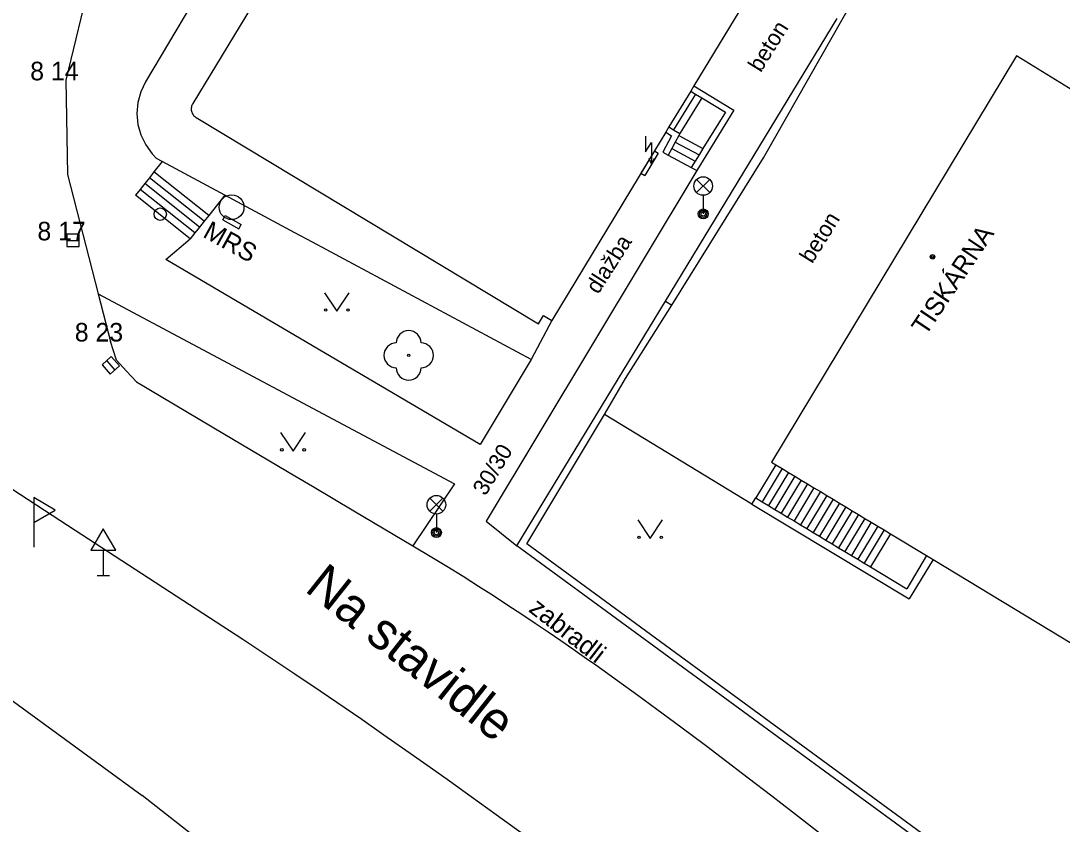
# Model space of a CAD drawing. Extents: x -538441 to -536770, y -1181008 to -1179809.
# Drawn here: x -538161.78 to -538119.74, y -1180887.51 to -1180855.09 of the extents above; entities that cross this region are included whole.
import ezdxf

# ---------------------------------------------------------------- set-up
doc = ezdxf.new("R2010")
doc.units = 0
for name, color, linetype in [('Vrstva 10', 7, 'Continuous'), ('Vrstva 11', 7, 'Continuous'), ('Vrstva 22', 7, 'Continuous'), ('Vrstva 24', 7, 'Continuous'), ('Vrstva 27', 7, 'Continuous'), ('Vrstva 28', 7, 'Continuous'), ('Vrstva 31', 7, 'Continuous'), ('Vrstva 33', 7, 'Continuous'), ('Vrstva 34', 7, 'Continuous'), ('Vrstva 36', 7, 'Continuous'), ('Vrstva 39', 7, 'Continuous'), ('Vrstva 4', 7, 'Continuous'), ('Vrstva 40', 7, 'Continuous'), ('Vrstva 41', 7, 'Continuous'), ('Vrstva 49', 7, 'Continuous'), ('Vrstva 5', 7, 'Continuous'), ('Vrstva 7', 7, 'Continuous'), ('Vrstva 8', 7, 'Continuous')]:
    doc.layers.add(name, color=color, linetype=linetype)

msp = doc.modelspace()

# ---------------------------------------------------------------- linework, layer by layer
at = {"layer": 'Vrstva 10'}
for p, q in [((-538158.99, -1180853.47), (-538159.96, -1180857.49)), ((-538159.96, -1180857.49), (-538159.89, -1180861.29)), ((-538159.58, -1180875.66), (-538166.34, -1180871.26)), ((-538152.82, -1180880.06), (-538159.58, -1180875.66))]:
    msp.add_line(p, q, dxfattribs=at)
for points in [[(-538159.89, -1180861.29), (-538158.655, -1180866.101), (-538158.16, -1180868.03)], [(-538157.11, -1180869.66), (-538157.51, -1180869.22), (-538157.91, -1180868.78), (-538158.16, -1180868.03)], [(-538157.11, -1180869.66), (-538153.555, -1180871.766), (-538150.718, -1180873.446)], [(-538150.718, -1180873.446), (-538150, -1180873.871), (-538148.334, -1180874.858), (-538145.95, -1180876.27), (-538145.251, -1180876.688), (-538144.577, -1180877.1), (-538143.927, -1180877.503), (-538143.301, -1180877.899), (-538142.698, -1180878.286)], [(-538142.698, -1180878.286), (-538142.115, -1180878.665), (-538141.553, -1180879.036), (-538141.011, -1180879.399), (-538140.487, -1180879.752), (-538139.982, -1180880.098), (-538139.494, -1180880.435), (-538139.022, -1180880.763), (-538138.566, -1180881.083), (-538137.687, -1180881.709), (-538136.866, -1180882.301), (-538136.1, -1180882.86), (-538135.384, -1180883.389), (-538134.715, -1180883.887)], [(-538150.718, -1180881.448), (-538151.406, -1180880.99), (-538152.82, -1180880.06)], [(-538144.474, -1180885.775), (-538145.248, -1180885.225), (-538145.926, -1180884.746), (-538147.117, -1180883.911), (-538148.013, -1180883.289), (-538148.687, -1180882.826), (-538149.7, -1180882.134), (-538150.718, -1180881.448)], [(-538134.715, -1180883.887), (-538134.089, -1180884.356)], [(-538134.089, -1180884.356), (-538133.504, -1180884.799), (-538132.409, -1180885.632), (-538131.455, -1180886.366), (-538130.621, -1180887.01), (-538129.166, -1180888.143)], [(-538136.93, -1180891.271), (-538138.634, -1180890.014), (-538140.127, -1180888.918), (-538141.437, -1180887.964), (-538142.584, -1180887.132), (-538143.591, -1180886.407), (-538144.474, -1180885.775)]]:
    msp.add_lwpolyline(points, dxfattribs=at)
at = {"layer": 'Vrstva 11'}
for p, q in [((-538134.605, -1180857.711), (-538132.99, -1180858.69)), ((-538134.542, -1180858.042), (-538135.427, -1180859.482)), ((-538134.285, -1180858.198), (-538135.171, -1180859.639)), ((-538132.99, -1180858.69), (-538134.49, -1180861.13)), ((-538135.504, -1180859.73), (-538135.86, -1180860.39)), ((-538135.741, -1180859.586), (-538135.504, -1180859.73)), ((-538135.213, -1180859.717), (-538134.238, -1180860.242)), ((-538135.498, -1180860.245), (-538134.553, -1180860.754)), ((-538135.355, -1180859.981), (-538134.395, -1180860.498)), ((-538135.86, -1180860.39), (-538135.64, -1180860.509)), ((-538135.64, -1180860.509), (-538134.71, -1180861.01)), ((-538154.195, -1180862.939), (-538156.405, -1180861.189)), ((-538134.49, -1180861.13), (-538142.99, -1180875.28)), ((-538134.71, -1180861.01), (-538134.49, -1180861.13)), ((-538154.381, -1180863.174), (-538156.591, -1180861.424)), ((-538154.753, -1180863.644), (-538156.963, -1180861.894)), ((-538154.567, -1180863.409), (-538156.777, -1180861.659)), ((-538154.94, -1180863.88), (-538157.15, -1180862.13)), ((-538155.92, -1180864.72), (-538154.94, -1180863.88)), ((-538150, -1180868.208), (-538155.92, -1180864.72)), ((-538158.655, -1180866.101), (-538150, -1180870.715)), ((-538143.24, -1180872.19), (-538150, -1180868.208)), ((-538141.18, -1180868.76), (-538143.24, -1180872.19)), ((-538150, -1180870.715), (-538144.27, -1180873.77)), ((-538132.26, -1180874.6), (-538138.22, -1180870.97)), ((-538131.3, -1180873.004), (-538132.106, -1180874.343)), ((-538131.042, -1180873.158), (-538131.848, -1180874.498)), ((-538130.784, -1180873.312), (-538131.59, -1180874.652)), ((-538144.27, -1180873.77), (-538145.95, -1180876.27)), ((-538130.527, -1180873.467), (-538131.333, -1180874.807)), ((-538130.27, -1180873.621), (-538131.076, -1180874.961)), ((-538130.013, -1180873.776), (-538130.819, -1180875.116)), ((-538129.756, -1180873.931), (-538130.562, -1180875.271)), ((-538129.499, -1180874.085), (-538130.305, -1180875.425)), ((-538129.242, -1180874.24), (-538130.048, -1180875.58)), ((-538132.26, -1180874.6), (-538132.106, -1180874.343)), ((-538132.26, -1180874.6), (-538125.908, -1180878.415)), ((-538128.985, -1180874.395), (-538129.791, -1180875.735)), ((-538128.728, -1180874.549), (-538129.534, -1180875.889)), ((-538128.471, -1180874.704), (-538129.277, -1180876.044)), ((-538128.214, -1180874.858), (-538129.02, -1180876.198)), ((-538127.957, -1180875.013), (-538128.763, -1180876.353)), ((-538142.99, -1180875.28), (-538141.75, -1180876.28)), ((-538127.699, -1180875.168), (-538128.505, -1180876.508)), ((-538127.442, -1180875.322), (-538128.248, -1180876.662)), ((-538127.184, -1180875.476), (-538127.99, -1180876.816)), ((-538126.927, -1180875.631), (-538127.733, -1180876.971)), ((-538126.67, -1180875.785), (-538127.476, -1180877.125)), ((-538125.207, -1180876.671), (-538126.01, -1180878.004)), ((-538124.951, -1180876.826), (-538125.908, -1180878.415))]:
    msp.add_line(p, q, dxfattribs=at)
for points in [[(-538134.735, -1180857.925), (-538134.542, -1180858.042), (-538134.285, -1180858.198), (-538133.335, -1180858.774)], [(-538133.335, -1180858.774), (-538134.238, -1180860.242), (-538134.395, -1180860.498), (-538134.553, -1180860.754), (-538134.71, -1180861.01)], [(-538135.611, -1180859.372), (-538135.427, -1180859.482), (-538135.171, -1180859.639)], [(-538135.171, -1180859.639), (-538135.213, -1180859.717), (-538135.355, -1180859.981), (-538135.498, -1180860.245), (-538135.64, -1180860.509)], [(-538156.068, -1180860.765), (-538156.405, -1180861.189), (-538156.591, -1180861.424), (-538156.777, -1180861.659), (-538156.963, -1180861.894), (-538157.15, -1180862.13)], [(-538153.546, -1180862.119), (-538154.195, -1180862.939), (-538154.381, -1180863.174), (-538154.567, -1180863.409), (-538154.753, -1180863.644), (-538154.94, -1180863.88)], [(-538132.106, -1180874.343), (-538131.848, -1180874.498), (-538131.59, -1180874.652), (-538131.333, -1180874.807), (-538131.076, -1180874.961), (-538130.819, -1180875.116), (-538130.562, -1180875.271), (-538130.305, -1180875.425), (-538130.048, -1180875.58), (-538129.791, -1180875.735), (-538129.534, -1180875.889), (-538129.277, -1180876.044), (-538129.02, -1180876.198), (-538128.763, -1180876.353), (-538128.505, -1180876.508), (-538128.248, -1180876.662), (-538127.99, -1180876.816), (-538127.733, -1180876.971), (-538127.476, -1180877.125), (-538126.01, -1180878.004)]]:
    msp.add_lwpolyline(points, dxfattribs=at)
at = {"layer": 'Vrstva 22'}
msp.add_circle((-538146.12, -1180868.59), 0.05, dxfattribs=at)
for centre, start, end in [((-538146.12, -1180868.09), 0, 180), ((-538146.62, -1180868.59), 90, 270), ((-538145.62, -1180868.59), 270, 90), ((-538146.12, -1180869.09), 180, 0)]:
    msp.add_arc(centre, 0.5, start, end, dxfattribs=at)
at = {"layer": 'Vrstva 24'}
for p, q in [((-538136.56, -1180859.744), (-538136.56, -1180860.371)), ((-538136.198, -1180860.34), (-538136.742, -1180861.238)), ((-538136.56, -1180860.371), (-538136.31, -1180859.995)), ((-538136.31, -1180859.995), (-538136.31, -1180860.87)), ((-538136.198, -1180860.34), (-538136.046, -1180860.432)), ((-538136.046, -1180860.432), (-538136.59, -1180861.33)), ((-538136.419, -1180860.625), (-538136.31, -1180860.87)), ((-538136.31, -1180860.87), (-538136.199, -1180860.625)), ((-538136.742, -1180861.238), (-538136.59, -1180861.33)), ((-538153.63, -1180863.12), (-538153.533, -1180862.945)), ((-538153.63, -1180863.12), (-538152.98, -1180863.48)), ((-538153.533, -1180862.945), (-538152.883, -1180863.305)), ((-538152.98, -1180863.48), (-538152.883, -1180863.305))]:
    msp.add_line(p, q, dxfattribs=at)
at = {"layer": 'Vrstva 27'}
for p, q in [((-538159.92, -1180863.95), (-538159.42, -1180863.95)), ((-538158.313, -1180868.806), (-538157.981, -1180869.18))]:
    msp.add_line(p, q, dxfattribs=at)
for points in [[(-538159.92, -1180864.2), (-538159.42, -1180864.2), (-538159.42, -1180863.7), (-538159.92, -1180863.7)], [(-538158.5, -1180868.972), (-538158.168, -1180869.346), (-538157.794, -1180869.014), (-538158.126, -1180868.64)]]:
    msp.add_lwpolyline(points, close=True, dxfattribs=at)
msp.add_circle((-538153.27, -1180862.61), 0.5, dxfattribs=at)
at = {"layer": 'Vrstva 28'}
msp.add_circle((-538156.15, -1180862.89), 0.25, dxfattribs=at)
at = {"layer": 'Vrstva 31'}
msp.add_line((-538161.26, -1180875.331), (-538161.26, -1180876.33), dxfattribs=at)
msp.add_lwpolyline([(-538161.26, -1180874.33), (-538161.26, -1180875.331), (-538160.396, -1180874.831)], close=True, dxfattribs=at)
at = {"layer": 'Vrstva 33'}
for p, q in [((-538134.494, -1180862.021), (-538133.966, -1180861.491)), ((-538134.494, -1180861.491), (-538133.966, -1180862.021)), ((-538134.23, -1180862.13), (-538134.23, -1180862.88)), ((-538145.264, -1180874.881), (-538144.736, -1180874.351)), ((-538145.264, -1180874.351), (-538144.736, -1180874.881)), ((-538145, -1180874.99), (-538145, -1180875.74))]:
    msp.add_line(p, q, dxfattribs=at)
for centre, radius in [((-538134.23, -1180861.756), 0.375), ((-538134.23, -1180862.881), 0.2), ((-538134.23, -1180862.881), 0.145), ((-538134.23, -1180862.881), 0.0876), ((-538145, -1180874.616), 0.375), ((-538145, -1180875.741), 0.2), ((-538145, -1180875.741), 0.145), ((-538145, -1180875.741), 0.0876)]:
    msp.add_circle(centre, radius, dxfattribs=at)
at = {"layer": 'Vrstva 34'}
for p, q in [((-538158.449, -1180876.454), (-538158.449, -1180877.47)), ((-538158.699, -1180877.47), (-538158.199, -1180877.47))]:
    msp.add_line(p, q, dxfattribs=at)
msp.add_lwpolyline([(-538158.949, -1180876.454), (-538157.949, -1180876.454), (-538158.449, -1180875.586)], close=True, dxfattribs=at)
at = {"layer": 'Vrstva 36'}
for points in [[(-538149.52, -1180866.06), (-538149.02, -1180866.81), (-538148.52, -1180866.06)], [(-538151.29, -1180871.7), (-538150.79, -1180872.45), (-538150.29, -1180871.7)], [(-538136.87, -1180875.23), (-538136.37, -1180875.98), (-538135.87, -1180875.23)]]:
    msp.add_lwpolyline(points, dxfattribs=at)
for centre in [(-538149.47, -1180866.76), (-538148.571, -1180866.76), (-538151.24, -1180872.4), (-538150.341, -1180872.4), (-538136.82, -1180875.93), (-538135.921, -1180875.93)]:
    msp.add_circle(centre, 0.05, dxfattribs=at)
at = {"layer": 'Vrstva 39'}
for radius in [0.09, 0.0398]:
    msp.add_circle((-538124.97, -1180864.61), radius, dxfattribs=at)
at = {"layer": 'Vrstva 5'}
for p, q in [((-538145.118, -1180842.4), (-538154.831, -1180858.427)), ((-538121.58, -1180856.5), (-538131.475, -1180872.899)), ((-538118.5, -1180858.396), (-538121.58, -1180856.5)), ((-538156.74, -1180857.55), (-538156.933, -1180857.951)), ((-538156.933, -1180857.951), (-538157.051, -1180858.38)), ((-538157.051, -1180858.38), (-538157.091, -1180858.824)), ((-538157.091, -1180858.824), (-538157.051, -1180859.267)), ((-538154.7, -1180858.992), (-538140.882, -1180867.316)), ((-538157.051, -1180859.267), (-538156.933, -1180859.696)), ((-538156.933, -1180859.696), (-538156.739, -1180860.097)), ((-538156.739, -1180860.097), (-538156.477, -1180860.457)), ((-538156.477, -1180860.457), (-538156.3, -1180860.64)), ((-538140.882, -1180867.316), (-538140.678, -1180866.977)), ((-538140.678, -1180866.977), (-538140.344, -1180867.178)), ((-538140.344, -1180867.178), (-538141.18, -1180868.76))]:
    msp.add_line(p, q, dxfattribs=at)
for points in [[(-538153.038, -1180851.294), (-538156.74, -1180857.55)], [(-538130.748, -1180851.35), (-538134.605, -1180857.711)], [(-538134.605, -1180857.711), (-538134.735, -1180857.925)], [(-538134.735, -1180857.925), (-538135.611, -1180859.372)], [(-538154.831, -1180858.427), (-538154.852, -1180858.461), (-538154.869, -1180858.497), (-538154.882, -1180858.535), (-538154.891, -1180858.573), (-538154.897, -1180858.613), (-538154.899, -1180858.652), (-538154.896, -1180858.692), (-538154.89, -1180858.731), (-538154.88, -1180858.77), (-538154.865, -1180858.807), (-538154.848, -1180858.843), (-538154.827, -1180858.876)], [(-538154.827, -1180858.876), (-538154.802, -1180858.908), (-538154.774, -1180858.937), (-538154.744, -1180858.962), (-538154.712, -1180858.985), (-538154.7, -1180858.992)], [(-538135.611, -1180859.372), (-538135.741, -1180859.586)], [(-538135.741, -1180859.586), (-538136.198, -1180860.34)], [(-538136.198, -1180860.34), (-538140.344, -1180867.178)], [(-538156.068, -1180860.765), (-538156.3, -1180860.64)], [(-538153.546, -1180862.119), (-538156.068, -1180860.765)], [(-538150.718, -1180863.638), (-538153.546, -1180862.119)], [(-538150, -1180864.023), (-538150.718, -1180863.638)], [(-538141.18, -1180868.76), (-538150, -1180864.023)], [(-538131.475, -1180872.899), (-538131.3, -1180873.004)], [(-538131.3, -1180873.004), (-538131.042, -1180873.158)], [(-538131.042, -1180873.158), (-538130.784, -1180873.312)], [(-538130.784, -1180873.312), (-538130.527, -1180873.467)], [(-538130.527, -1180873.467), (-538130.27, -1180873.621)], [(-538130.27, -1180873.621), (-538130.013, -1180873.776)], [(-538130.013, -1180873.776), (-538129.756, -1180873.931)], [(-538129.756, -1180873.931), (-538129.499, -1180874.085)], [(-538129.499, -1180874.085), (-538129.242, -1180874.24)], [(-538129.242, -1180874.24), (-538128.985, -1180874.395)], [(-538128.985, -1180874.395), (-538128.728, -1180874.549)], [(-538128.728, -1180874.549), (-538128.471, -1180874.704)], [(-538128.471, -1180874.704), (-538128.214, -1180874.858)], [(-538128.214, -1180874.858), (-538127.957, -1180875.013)], [(-538127.957, -1180875.013), (-538127.699, -1180875.168)], [(-538127.699, -1180875.168), (-538127.442, -1180875.322)], [(-538127.442, -1180875.322), (-538127.184, -1180875.476)], [(-538127.184, -1180875.476), (-538126.927, -1180875.631)], [(-538126.927, -1180875.631), (-538126.67, -1180875.785)], [(-538126.67, -1180875.785), (-538125.207, -1180876.671)], [(-538125.207, -1180876.671), (-538124.951, -1180876.826)], [(-538124.951, -1180876.826), (-538119.34, -1180880.22)]]:
    msp.add_lwpolyline(points, dxfattribs=at)
at = {"layer": 'Vrstva 7'}
for p, q in [((-538131.8, -1180860.62), (-538128.14, -1180854.17)), ((-538135.754, -1180866.405), (-538128.82, -1180855)), ((-538135.498, -1180866.561), (-538131.8, -1180860.62)), ((-538137.36, -1180869.52), (-538135.498, -1180866.561)), ((-538138.22, -1180870.97), (-538137.36, -1180869.52)), ((-538141.351, -1180876.2), (-538138.22, -1180870.97)), ((-538124.383, -1180888.618), (-538141.351, -1180876.2)), ((-538163.72, -1180881.37), (-538156.88, -1180886.35))]:
    msp.add_line(p, q, dxfattribs=at)
for points in [[(-538141.75, -1180876.28), (-538135.754, -1180866.405)], [(-538135.754, -1180866.405), (-538135.498, -1180866.561)], [(-538124.56, -1180888.86), (-538141.75, -1180876.28)]]:
    msp.add_lwpolyline(points, dxfattribs=at)
at = {"layer": 'Vrstva 8'}
msp.add_line((-538154.31, -1180888.37), (-538156.88, -1180886.35), dxfattribs=at)

# ---------------------------------------------------------------- texts
at = {"layer": 'Vrstva 4'}
for s, p in [(' 8 14', (-538161.679, -1180857.49)), (' 8 17', (-538161.389, -1180863.95)), (' 8 23', (-538159.879, -1180868.03))]:
    msp.add_text(s, height=0.75, dxfattribs=at).set_placement(p)
at = {"layer": 'Vrstva 40'}
for s, rotation, p in [('beton', 58.1028, (-538131.908, -1180857.203)), ('beton', 58.1028, (-538129.83, -1180864.917)), ('dlažba', 57.3625, (-538138.468, -1180866.151)), ('30/30', 58.9074, (-538143.02, -1180874.291))]:
    msp.add_text(s, height=0.65, rotation=rotation, dxfattribs=at).set_placement(p)
at = {"layer": 'Vrstva 41'}
for s, rotation, p in [('MRS', 331.0203, (-538154.472, -1180863.79)), ('TISKÁRNA', 56.192, (-538125.247, -1180867.83)), ('zabradli', 322.2258, (-538141.316, -1180878.899))]:
    msp.add_text(s, height=0.75, rotation=rotation, dxfattribs=at).set_placement(p)
at = {"layer": 'Vrstva 49'}
msp.add_text('Na stavidle', height=1.5, rotation=321.4917, dxfattribs=at).set_placement((-538150.362, -1180878.073))

doc.saveas('drawing.dxf')
